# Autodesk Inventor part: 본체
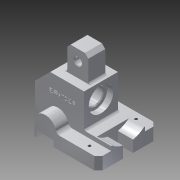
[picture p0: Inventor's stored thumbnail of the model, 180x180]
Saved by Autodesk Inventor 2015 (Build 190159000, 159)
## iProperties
Created: 2016-11
Part Number: 본체
Material: 알루미늄 6061
Document SubType Name: Modeling
Designer: LineLG02
Mass: 487.148 g
Surface Area: 258.421 cm^2
Volume: 180.425 cm^3
Density: 2.7 g/cm^3
Appearance: 알루미늄 - 평지
Author: LineLG02
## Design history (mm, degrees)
sketch "스케치1"
  geometry: L1 (-38, 35)-(33, 35); L2 (38, 30)-(38, -30); L3 (33, -35)-(-38, -35); L4 (-38, -35)-(-38, 35); L5 (-38, 35)-(38, -35); L6 (38, 35)-(-38, -35); L7 (33, 35)-(38, 30); L8 (38, -30)-(33, -35); 1 further point
  constraints: 16 end point, 4 point on line, 2 midpoint, 2 parallel, 1 horizontal, 1 perpendicular
  dimensions: "d0" = 76 distance of L5.end L3.end; "d1" = 70 distance of L6.start L5.end; "d2" = 5 distance of L1.end L6.start; "d3" = 5 distance of L2.start L6.start (= d2); "d4" = 5 distance of L2.end L5.end (= d2); "d5" = 5 distance of L3.start L5.end (= d4)
extrude "돌출1" new body sketch "스케치1" distance "d6" = 15; taper "d7" = 0 deg
sketch "스케치2"
  geometry: L1 (-52, 20)-(6, 20); L2 (-52, -20)-(6, -20); L3 (-52, -20)-(-52, 20); L4 (6, -20)-(6, 20); L5 (-38, -35)-(33, -35) reference; L6 (-38, 35)-(-38, -35) reference; 1 further point
  constraints: 8 end point, 1 horizontal, 1 parallel, 1 vertical
  dimensions: "d11" = 58 distance between parallel lines of L3 L4; "d12" = 15 distance between parallel lines of L2 L5; "d13" = 55 distance between parallel lines of L1 L5; "d14" = 44 distance between parallel lines of L6 L4
extrude "돌출2" join sketch "스케치2" distance "d15" = 45; taper "d16" = 0 deg
sketch "스케치3"
  geometry: L1 (76, 0)-(71, 0) reference; L2 (23, 0)-(23, 7); L3 (3, 0)-(3, 7); L4 (23, 0)-(3, 0); L5 (3, 7)-(23, 7); L6 (0, 0)-(0, 15) reference; L7 (71, 0)-(0, 0) reference; L8 (-14, 60)-(44, 60) reference; L9 (76, 0)-(76, 15) reference; 1 further point
  constraints: 8 end point, 2 horizontal
  dimensions: "d21" = 3 distance between parallel lines of L6 L3; "d23" = 7 distance between parallel lines of L4 L5; "d24" = 53 distance between parallel lines of L8 L5; "d26" = 53 distance between parallel lines of L9 L2
extrude "돌출3" cut sketch "스케치3" distance "d27" = 200; taper "d28" = 0 deg
sketch "스케치4"
  geometry: L1 (6, 20)-(6, -20) reference; L2 (6, -20)-(6, 20); L3 (-38, -20)-(-38, -35) reference; L4 (38, 30)-(38, -30) reference; L5 (6, -20)-(38, -20); L6 (38, -20)-(38, 20); L7 (38, 20)-(6, 20); 1 further point
  constraints: 8 end point, 2 point on line, 1 collinear
  dimensions: "d29" = 32 distance of L1.end L5.end; "d30" = 40 distance of L5.end L6.end
extrude "돌출4" join sketch "스케치4" distance "d31" = 5; taper "d32" = 0 deg
sketch "스케치5"
  geometry: L1 (52, 60)-(52, 15) reference; L2 (52, 15)-(38, 15) reference; L3 (38, 15)-(38, 0) reference; L4 (38, 0)-(35, 0) reference; L5 (35, 0)-(35, 7) reference; L6 (35, 7)-(15, 7) reference; L7 (15, 7)-(15, 0) reference; L8 (15, 0)-(-38, 0) reference; L9 (-38, 0)-(-38, 20) reference; L10 (-38, 20)-(-6, 20) reference; L11 (-6, 20)-(-6, 60) reference; L12 (-6, 60)-(52, 60) reference; L13 (52, 15)-(52, 12); L14 (52, 12)-(38, 12); 1 further point
  constraints: 4 end point, 2 point on line, 1 perpendicular, 1 vertical
  dimensions: "d33" = 48 distance of L1.start L13.end; "d34" = 14 distance between parallel lines of L3 L13
extrude "돌출5" join sketch "스케치5" stored distance "d35" = 40; taper "d36" = 0 deg
chamfer "모따기1" distance "d37" = 4; stored, may be unused: second distance "d38" = 2, angle "d39" = 45 deg
sketch "스케치6"
  geometry: L1 (-10, -3)-(-14, 1) reference; L2 (-10, -3)-(0, -3) reference; L3 (0, 0)-(0, -3) reference; L4 (76, 0)-(0, 0) reference; L5 (76, 0)-(76, 5) reference; L6 (44, 5)-(76, 5) reference; L7 (44, 5)-(44, 45) reference; L8 (-14, 45)-(44, 45) reference; L9 (-14, 45)-(-14, 1) reference; L10 (-14, 45)-(-14, 1) reference; L11 (-14, 27)-(4, 45); 1 further point
  constraints: 2 end point, 2 point on line
  dimensions: "d44" = 45 deg angle of L9 L11; "d45" = 30 vertical distance of L11.start L1.start
extrude "돌출6" cut sketch "스케치6" distance "d46" = 40; taper "d47" = 0 deg
sketch "스케치7"
  geometry: L1 (-34, -20)-(-34, 20) reference; L2 (-34, 20)-(6, 20) reference; L3 (6, 20)-(6, -20) reference; L4 (6, -20)-(-34, -20) reference; L5 (1, 10)-(-24, 10); L6 (1, -10)-(-24, -10); L7 (-24, -10)-(-24, 10); L8 (1, -10)-(1, 10); 1 further point
  constraints: 8 end point, 2 vertical
  dimensions: "d52" = 5 distance between parallel lines of L3 L8; "d53" = 10 distance between parallel lines of L2 L5; "d54" = 10 distance between parallel lines of L1 L7; "d55" = 10 distance between parallel lines of L4 L6
extrude "돌출7" join sketch "스케치7" distance "d56" = 30; taper "d57" = 0 deg
node "스케치8"
sketch "스케치9"
  geometry: L1 (26, 0)-(26, 40) reference; L2 (0, 40)-(26, 40) reference; L3 (0, 0)-(0, 40) reference; L4 (26, 0)-(0, 0) reference; L5 (26, 0)-(26, 40) reference; C1 r 10 at (26, 20); 1 further point
  constraints: 1 centre point, 1 midpoint
  dimensions: "d58" = 20 diameter of C1
extrude "돌출8" cut sketch "스케치9" distance "d59" = 200; taper "d60" = 0 deg
sketch "스케치10"
  geometry: L1 (40, 0)-(40, 40) reference; L2 (40, 40)-(0, 40) reference; L3 (0, 0)-(0, 40) reference; L4 (40, 0)-(0, 0) reference; C1 r 10 at (18, 20) reference; C2 r 14.5 at (18, 20); 1 further point
  constraints: 1 centre point, 1 coincident
  dimensions: "d61" = 29 diameter of C2
extrude "돌출9" cut sketch "스케치10" distance "d62" = 7; taper "d63" = 0 deg
chamfer "모따기2" distance "d64" = 1; stored, may be unused: second distance "d65" = 2, angle "d66" = 45 deg
chamfer "모따기3" distance "d67" = 4; stored, may be unused: second distance "d68" = 2, angle "d69" = 45 deg
sketch "스케치11"
  geometry: L1 (23, -15)-(23, -8) reference; L2 (23, -8)-(3, -8) reference; L3 (3, -8)-(3, -15) reference; L4 (3, -15)-(0, -15) reference; L5 (0, -15)-(0, 0) reference; L6 (0, 0)-(71, 0) reference; L7 (71, 0)-(71, -15) reference; L8 (71, -15)-(23, -15) reference; A1 r 13 centre (13, 0) between (26, 0) and (0, 0); 1 further point
  constraints: 2 point on circle, 1 centre point, 1 end point, 1 point on line
  dimensions: "d71" = 13 radius of A1; "d72" = 8 vertical distance of L1.end A1.centre
extrude "돌출10" join sketch "스케치11" distance "d73" = 70; taper "d74" = 0 deg
fillet "모깎기1" dims "d75" = 5
sketch "스케치12"
  geometry: L1 (0, 60)-(0, 0) reference; L2 (0, 0)-(-15, 0) reference; L3 (-15, 0)-(-15, 10) reference; L4 (-15, 10)-(-20, 10) reference; L5 (-20, 10)-(-20, 50) reference; L6 (-20, 50)-(-15, 50) reference; L7 (-15, 50)-(-15, 60) reference; L8 (-15, 60)-(0, 60) reference; C1 r 11 at (-42, 30) reference; A1 r 29 centre (-42, 30) between (-20, 11.106) and (-20, 48.894); 1 further point
  constraints: 2 point on circle, 2 point on line, 1 centre point, 1 coincident
  dimensions: "d76" = 29 radius of A1
extrude "돌출11" cut sketch "스케치12" distance "d77" = 18; taper "d78" = 0 deg
sketch "스케치13"
  geometry: L1 (15, -35)-(15, 35) reference; L2 (15, 35)-(-33, 35) reference; L3 (-33, 35)-(-38, 30) reference; L4 (-38, 30)-(-38, -30) reference; L5 (-38, -30)-(-33, -35) reference; L6 (-33, -35)-(15, -35) reference; L7 (-38, 6)-(-20, 6); L8 (-38, -6)-(-20, -6); L9 (-20, -6)-(-20, 6); L10 (-38, -6)-(-38, 6); L11 (-38, -18.894)-(-38, 18.894) reference; 1 further point
  constraints: 8 end point, 1 collinear, 1 vertical
  dimensions: "d82" = 12 distance between parallel lines of L7 L8; "d83" = 18 distance between parallel lines of L4 L9; "d84" = 38 horizontal distance of L7.start point (0, 0); "d85" = 6 distance from line of point (0, 0) L8; "d86" = 6 vertical distance of point (0, 0) L7.end
extrude "돌출12" cut sketch "스케치13" distance "d87" = 18; taper "d88" = 0 deg
fillet "모깎기2" dims "d89" = 3
fillet "모깎기3" dims "d90" = 3
sketch "스케치14"
  geometry: L1 (-7.708, -35)-(-7.708, -20) reference; L2 (-7.708, -35)-(33, -35) reference; L3 (33, -35)-(38, -30) reference; L4 (38, -30)-(38, -20) reference; L5 (38, -20)-(-7.708, -20) reference; L6 (-7.708, 20)-(-7.708, 35) reference; L7 (-7.708, 20)-(38, 20) reference; L8 (38, 20)-(38, 30) reference; L9 (38, 30)-(33, 35) reference; L10 (33, 35)-(-7.708, 35) reference; 3 further points
  dimensions: "d94" = 18 distance from line of L4 point (20, -27.5); "d95" = 55 distance of point (20, 27.5) point (20, -27.5); "d96" = 18 horizontal distance of L8.end point (20, 27.5); "d97" = 27.5 vertical distance of point (0, 0) point (20, 27.5)
hole "구멍1" sketch "스케치14" at (20, -27.5), (20, 27.5) diameter "d98" = 3.242; stored, may be unused: countersink angle "d102" = 90 deg, drill point angle "d104" = 118 deg; dims "d99" = 8, "d100" = 4, "d101" = 2, "d103" = 11.8
sketch "스케치15"
  geometry: L1 (2, 52)-(1, 53) reference; L2 (1, 53)-(1, 56.5) reference; L3 (1, 56.5)-(-6, 56.5) reference; L4 (-6, 56.5)-(-6, 60) reference; L5 (-6, 60)-(-4, 60) reference; L6 (-1, 63)-(-1, 86) reference; L7 (-1, 86)-(3, 90) reference; L8 (3, 90)-(20, 90) reference; L9 (20, 90)-(24, 86) reference; L10 (24, 86)-(24, 63) reference; L11 (27, 60)-(34, 60) reference; L12 (34, 60)-(42, 52) reference; L13 (42, 52)-(2, 52) reference; L14 (1, 31)-(2, 32) reference; L15 (2, 32)-(52, 32) reference; L16 (52, 32)-(52, 16) reference; L17 (52, 16)-(48, 12) reference; L18 (48, 12)-(38, 12) reference; L19 (38, 12)-(38, 0) reference; L20 (38, 0)-(35, 0) reference; L21 (35, 0)-(35, 7) reference; L22 (35, 7)-(15, 7) reference; L23 (15, 7)-(15, 0) reference; L24 (15, 0)-(-20, 0) reference; L25 (-20, 0)-(-20, 20) reference; L26 (-20, 20)-(-9, 20) reference; L27 (-6, 23)-(-6, 27.5) reference; L28 (-6, 27.5)-(1, 27.5) reference; L29 (1, 27.5)-(1, 31) reference; C1 r 4 at (11.5, 77); A1 r 3 centre (-4, 63) between (-4, 60) and (-1, 63) reference; A2 r 3 centre (27, 63) between (24, 63) and (27, 60) reference; A3 r 3 centre (-9, 23) between (-9, 20) and (-6, 23) reference; 1 further point
  constraints: 1 centre point
  dimensions: "d107" = 4 radius of C1; "d108" = 77 vertical distance of point (0, 0) C1.centre; "d109" = 12.5 horizontal distance of L9.end C1.centre
extrude "돌출13" cut sketch "스케치15" stored distance "d110" = 20; taper "d111" = 0 deg
chamfer "모따기4" distance "d112" = 1; stored, may be unused: second distance "d113" = 2, angle "d114" = 45 deg
sketch "스케치16"
  geometry: L1 (-90, 1)-(-90, 27) reference; L2 (-90, 27)-(-72, 45) reference; L3 (-72, 45)-(-32, 45) reference; L4 (-32, 45)-(-32, 8) reference; L5 (-29, 5)-(0, 5) reference; L6 (0, 5)-(0, 0) reference; L7 (0, 0)-(0, -15) reference; L8 (0, -15)-(-53, -15) reference; L9 (-53, -15)-(-53, -8) reference; L10 (-53, -8)-(-73, -8) reference; L11 (-73, -8)-(-73, -15) reference; L12 (-73, -15)-(-76, -15) reference; L13 (-76, -15)-(-76, -3) reference; L14 (-76, -3)-(-86, -3) reference; L15 (-86, -3)-(-90, 1) reference; L16 (-45.708, 0)-(0, 0) reference; L17 (-76, -3)-(-76, 0) reference; A1 r 3 centre (-29, 8) between (-32, 8) and (-29, 5) reference; A2 r 5 centre (-45.708, 5) between (-50.512, 3.611) and (-45.708, 0) reference; A3 r 13 centre (-63, 0) between (-50.512, 3.611) and (-76, 0) reference; 2 further points
  constraints: 1 other
  dimensions: "d115" = 25 horizontal distance of L3.end point (-57, 27); "d116" = 18 vertical distance of L2.end point (-57, 27)
feature "엠보싱1" sketch "스케치16" dims "d0" = 76, "d1" = 70, "d2" = 5, "d3" = 5 (= d2), "d4" = 5 (= d2), "d5" = 5 (= d4), "d11" = 58, "d12" = 15, "d13" = 55, "d14" = 44, "d117" = 0.5, "d118" = 0
node "솔리드1"
node "투영된 루프1"
node "투영된 루프2"
node "투영된 루프3"
node "투영된 루프4"
node "투영된 루프5"
node "투영된 루프6"
node "절단 모서리 투영1"
node "절단 모서리 투영2"
node "절단 모서리 투영3"
node "절단 모서리 투영4"
node "절단 모서리 투영5"
node "절단 모서리 투영6"
other parameters: "d70" = 13
